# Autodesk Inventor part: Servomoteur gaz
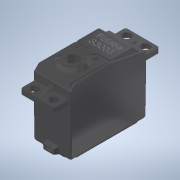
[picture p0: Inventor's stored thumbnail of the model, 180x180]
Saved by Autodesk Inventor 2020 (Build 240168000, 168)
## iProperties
Created: 2002-09
Part Number: Servomoteur gaz
Material: Générique
Document SubType Name: Modélisation
Designer: GAUTHERON
Density: 1 g/cm^3
Appearance: Plastique (Noir)
Control State: 0
Master: False
Checked Out: False
Shininess: 20.0
Angle Display Precision: 2
Document Length Units: 11270
Document Angle Units: 11279
Document Time Units: 11290
Document Mass Units: 11283
Document Length Units Precision: 3
Document Angle Units Precision: 2
Compacted: True
Density: 0.0
Volumn: 0.0
Area: 0.0
PropertySet Name: Model Information
Author: GAUTHERON
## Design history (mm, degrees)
feature "Base1"
sketch "Esquisse1"
  geometry: L1 (15.68, 0)-(0, 0) reference; L2 (1.757, -3.791)-(1.757, -0.791); L3 (1.757, -0.791)-(3.757, -0.791); L4 (3.757, -0.791)-(3.757, -1.139); L5 (3.757, -1.139)-(2.148, -1.139); L6 (2.148, -1.139)-(2.148, -2.096); L7 (2.148, -2.096)-(3.496, -2.096); L8 (3.496, -2.096)-(3.496, -2.443); L9 (3.496, -2.443)-(2.148, -2.443); L10 (2.148, -2.443)-(2.148, -3.791); L11 (2.148, -3.791)-(1.757, -3.791); L12 (5.583, -3.791)-(5.583, -3.437); L13 (4.278, -2.961)-(4.278, -1.617); L14 (4.278, -1.617)-(4.67, -1.617); L15 (4.67, -1.617)-(4.67, -2.8); L16 (5.583, -2.76)-(5.583, -1.617); L17 (5.583, -1.617)-(5.974, -1.617); L18 (5.974, -1.617)-(5.974, -3.791); L19 (5.974, -3.791)-(5.583, -3.791); L20 (7.365, -3.477)-(7.409, -3.801); L21 (6.626, -3.185)-(6.626, -1.965); L22 (6.626, -1.965)-(6.365, -1.965); L23 (6.365, -1.965)-(6.365, -1.617); L24 (6.365, -1.617)-(6.626, -1.617); L25 (6.626, -1.617)-(6.626, -1.081); L26 (6.626, -1.081)-(7.018, -0.861); L27 (7.018, -0.861)-(7.018, -1.617); L28 (7.018, -1.617)-(7.365, -1.617); L29 (7.365, -1.617)-(7.365, -1.965); L30 (7.365, -1.965)-(7.018, -1.965); L31 (7.018, -1.965)-(7.018, -3.195); L32 (8.061, -2.269)-(7.67, -2.226); L33 (9.452, -2.381)-(9.452, -2.848); L34 (9.583, -3.791)-(9.192, -3.791); L35 (9.016, -2.861)-(9.018, -2.748); L36 (10.409, -3.791)-(10.018, -3.791); L37 (10.018, -3.791)-(10.018, -0.791); L38 (10.018, -0.791)-(10.409, -0.791); L39 (10.409, -0.791)-(10.409, -1.91); L40 (10.409, -3.466)-(10.409, -3.791); L41 (12.67, -2.269)-(12.278, -2.226); L42 (14.061, -2.381)-(14.061, -2.848); L43 (14.192, -3.791)-(13.8, -3.791); L44 (13.624, -2.861)-(13.626, -2.748); 147 further points
  constraints: 86 end point, 215 other
extrude "Extrusion1" cut sketch "Esquisse1" distance "d0" = 1; taper "d1" = 0 deg
sketch "Esquisse2"
  geometry: L1 (15.042, -8.045)-(0.64, -8.045) reference; L2 (1.991, -7.001)-(2.383, -7.001); L3 (4.252, -5.915)-(3.861, -5.915); L4 (4.731, -7.262)-(5.122, -7.219); L5 (5.47, -6.61)-(5.51, -6.262); L6 (5.165, -5.871)-(4.774, -5.828); L7 (11.644, -7.262)-(12.035, -7.219); L8 (12.383, -6.61)-(12.423, -6.262); L9 (12.078, -5.871)-(11.687, -5.828); 184 further points
  constraints: 16 end point, 3 point on line, 251 other
extrude "Extrusion2" cut sketch "Esquisse2" distance "d2" = 1; taper "d3" = 0 deg
node "Solide1"
node "Corps solides"
node "Corps surfaciques"
